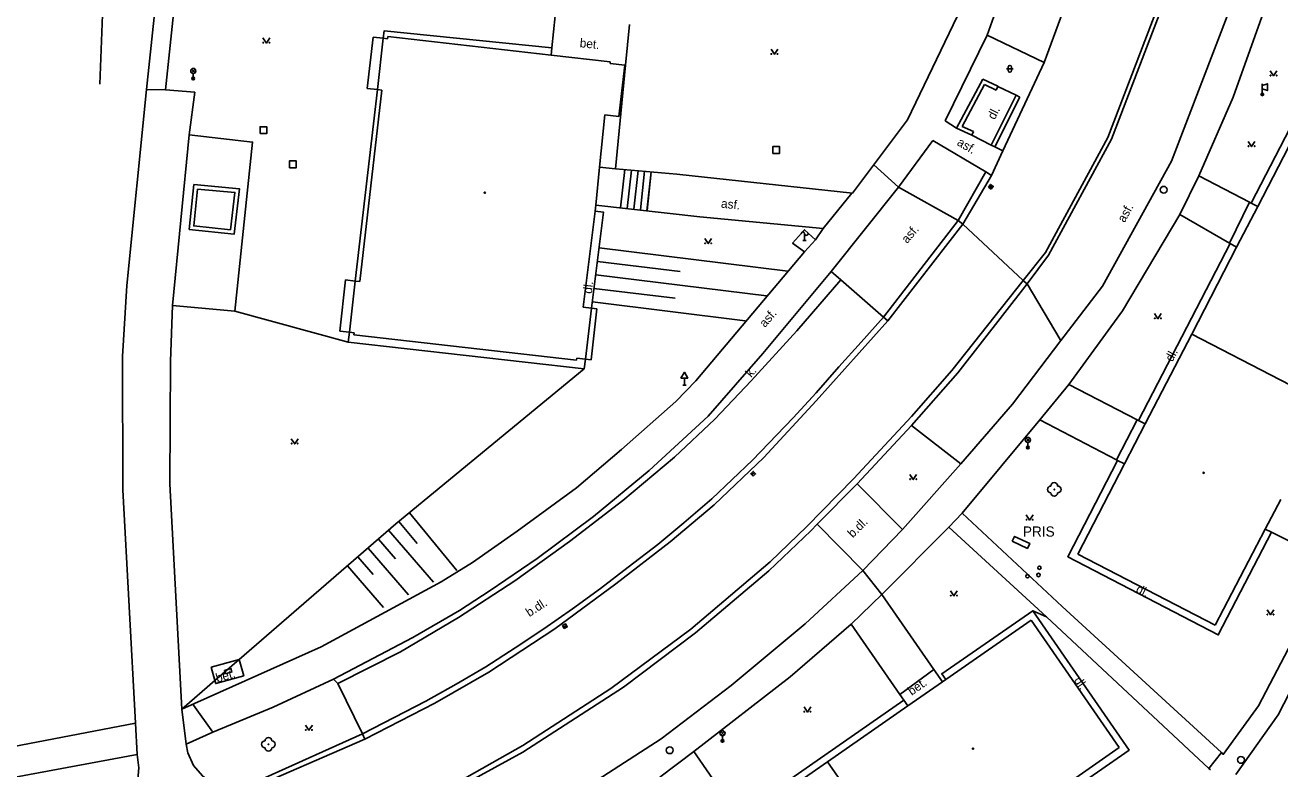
# Model space of a CAD drawing. Extents: x -602419 to -601554, y -1162937 to -1162362.
# Drawn here: x -601838.6 to -601746.3, y -1162548.7 to -1162494 of the extents above; entities that cross this region are included whole.
import ezdxf

# ---------------------------------------------------------------- set-up
doc = ezdxf.new("R2010")
doc.units = 0
doc.layers.add('Podklad', color=7, linetype='Continuous')

msp = doc.modelspace()

# ---------------------------------------------------------------- linework, layer by layer
at = {"layer": 'Podklad'}
for p, q in [((-601826.3725, -1162497.51), (-601826.1075, -1162497.245)), ((-601826.3725, -1162497.245), (-601826.1075, -1162497.51)), ((-601826.24, -1162497.565), (-601826.24, -1162497.94)), ((-601766.433, -1162497.228), (-601765.933, -1162497.228)), ((-601766.308, -1162497.103), (-601766.308, -1162497.353)), ((-601766.058, -1162497.103), (-601766.058, -1162497.353)), ((-601747.62, -1162499), (-601747.62, -1162498.325)), ((-601767.6543, -1162506.0005), (-601767.5057, -1162505.7995)), ((-601781.28, -1162509.85), (-601781.28, -1162509.35)), ((-601781.155, -1162509.85), (-601781.405, -1162509.85)), ((-601790.245, -1162520.48), (-601789.995, -1162520.48)), ((-601790.12, -1162519.971), (-601790.12, -1162520.48)), ((-601764.9925, -1162524.65), (-601764.7275, -1162524.385)), ((-601764.9925, -1162524.385), (-601764.7275, -1162524.65)), ((-601764.86, -1162524.705), (-601764.86, -1162525.08)), ((-601785.1504, -1162527.0964), (-601784.9696, -1162526.9236)), ((-601799.0184, -1162538.282), (-601798.8014, -1162538.1578)), ((-601787.4525, -1162546.22), (-601787.1875, -1162545.955)), ((-601787.4525, -1162545.955), (-601787.1875, -1162546.22)), ((-601787.32, -1162546.275), (-601787.32, -1162546.65))]:
    msp.add_line(p, q, dxfattribs=at)
for points in [[(-601718.62, -1162386.7199), (-601719.1599, -1162386.65), (-601718.15, -1162413.82), (-601705.36, -1162413.11), (-601705.25, -1162448.94), (-601717.05, -1162449.02), (-601716.04, -1162480.32), (-601716.4099, -1162484.2199), (-601717.94, -1162489.4099), (-601746.45, -1162544.74), (-601749.56, -1162549.13)], [(-601763.6599, -1162496.77), (-601760.48, -1162488.08), (-601756.88, -1162477.28)], [(-601848, -1162480.38), (-601847.54, -1162480.87), (-601842.9, -1162481.43), (-601833.56, -1162485.27), (-601831.9699, -1162485.6), (-601828.34, -1162485.99), (-601829.67, -1162498.74), (-601831.12, -1162513.1599), (-601831.45, -1162518.38), (-601831.42, -1162528.19), (-601830.48, -1162545.34)], [(-601833.1, -1162498.35), (-601832.63, -1162485.58), (-601829.24, -1162485.94)], [(-601828.28, -1162498.78), (-601826.96, -1162486.1599)], [(-601764.78, -1162486.14), (-601767.86, -1162494.76)], [(-601753.73, -1162488.54), (-601758.99, -1162502.27), (-601763.57, -1162510.73), (-601765.2151, -1162512.8049), (-601770.46, -1162519.42), (-601773.43, -1162522.8), (-601777.69, -1162527.38), (-601781.11, -1162530.89), (-601783.81, -1162533.48), (-601789.65, -1162538.44), (-601795.53, -1162542.8), (-601801.99, -1162546.98), (-601807.25, -1162549.95), (-601810.9, -1162551.81), (-601819.27, -1162555.34), (-601821.43, -1162556.31)], [(-601753.44, -1162488.63), (-601758.71, -1162502.4), (-601763.35, -1162510.94), (-601764.92, -1162513.03), (-601770.02, -1162519.59), (-601773.42, -1162523.45)], [(-601769.8, -1162526.28), (-601765.98, -1162521.88), (-601762.4303, -1162517.217), (-601759.38, -1162513.21), (-601754.29, -1162504.02), (-601748.9, -1162489.95)], [(-601746.9099, -1162491.32), (-601749.77, -1162499.32), (-601752.3, -1162505.09)], [(-601790.68, -1162504.9699), (-601777.76, -1162506.38), (-601773.7199, -1162500.98), (-601769.74, -1162492.7199)], [(-601799.87, -1162495.69), (-601799.63, -1162493.34)], [(-601794.16, -1162493.96), (-601794.45, -1162496.96), (-601795.18, -1162504.57)], [(-601813.44, -1162498.67), (-601813.01, -1162494.89)], [(-601813.01, -1162494.89), (-601812.27, -1162494.9699)], [(-601812.27, -1162494.9699), (-601812.21, -1162494.44), (-601799.87, -1162495.69)], [(-601811.95, -1162495.01), (-601811.93, -1162494.84)], [(-601811.93, -1162494.84), (-601799.92, -1162496.21)], [(-601767.86, -1162494.76), (-601770.95, -1162501.04)], [(-601763.6599, -1162496.77), (-601767.86, -1162494.76)], [(-601748.44, -1162507.1), (-601741.68, -1162494.03)], [(-601821.11, -1162494.955), (-601820.86, -1162495.33), (-601820.61, -1162494.955)], [(-601812.7, -1162498.75), (-601812.27, -1162494.9699)], [(-601811.95, -1162495.01), (-601812.27, -1162494.9699)], [(-601799.92, -1162496.21), (-601799.87, -1162495.69)], [(-601783.75, -1162495.7849), (-601783.5, -1162496.1599), (-601783.25, -1162495.7849)], [(-601799.92, -1162496.21), (-601795.57, -1162496.7)], [(-601795.57, -1162496.7), (-601795.58, -1162496.84)], [(-601766.69, -1162503.25), (-601763.6599, -1162496.77)], [(-601795.58, -1162496.84), (-601794.51, -1162496.96)], [(-601794.51, -1162496.96), (-601794.94, -1162500.73)], [(-601794.51, -1162496.96), (-601794.45, -1162496.96)], [(-601747.04, -1162497.365), (-601746.79, -1162497.74), (-601746.54, -1162497.365)], [(-601770.11, -1162501.6), (-601768.18, -1162497.98)], [(-601769.7, -1162501.46), (-601768.05, -1162498.38)], [(-601768.18, -1162497.98), (-601767.08, -1162498.51)], [(-601768.05, -1162498.38), (-601767.2, -1162498.79)], [(-601767.2, -1162498.79), (-601767.07, -1162498.52)], [(-601767.08, -1162498.51), (-601767.07, -1162498.52)], [(-601767.07, -1162498.52), (-601765.71, -1162499.17)], [(-601747.62, -1162498.45), (-601747.245, -1162498.325), (-601747.245, -1162498.825), (-601747.62, -1162498.7)], [(-601828.28, -1162498.78), (-601829.67, -1162498.74)], [(-601826.12, -1162498.94), (-601828.28, -1162498.78)], [(-601826.53, -1162502.08), (-601826.12, -1162498.94)], [(-601814.32, -1162512.83), (-601812.7, -1162498.75)], [(-601813.98, -1162512.87), (-601812.38, -1162498.79)], [(-601812.7, -1162498.75), (-601813.44, -1162498.67)], [(-601812.38, -1162498.79), (-601812.7, -1162498.75)], [(-601765.71, -1162499.17), (-601767.56, -1162502.83)], [(-601765.44, -1162499.3), (-601767.3, -1162502.96)], [(-601765.71, -1162499.17), (-601765.44, -1162499.3)], [(-601795.9699, -1162500.61), (-601796.36, -1162504.46)], [(-601794.94, -1162500.73), (-601795.9699, -1162500.61)], [(-601770.95, -1162501.04), (-601770.11, -1162501.6)], [(-601747.95, -1162507.35), (-601744.53, -1162500.75)], [(-601826.53, -1162502.08), (-601821.88, -1162502.61), (-601823.17, -1162515.06), (-601827.76, -1162514.62)], [(-601827.76, -1162514.62), (-601826.53, -1162502.08)], [(-601768.99, -1162502.11), (-601770.11, -1162501.6)], [(-601768.87, -1162501.84), (-601769.7, -1162501.46)], [(-601768.99, -1162502.11), (-601768.87, -1162501.84)], [(-601767.56, -1162502.83), (-601768.99, -1162502.11)], [(-601771.85, -1162502.5), (-601774.38, -1162505.92), (-601779.32, -1162512.13)], [(-601771.85, -1162502.5), (-601767.95, -1162504.81)], [(-601767.3, -1162502.96), (-601767.56, -1162502.83)], [(-601767.3, -1162502.96), (-601766.69, -1162503.25)], [(-601748.6599, -1162502.565), (-601748.4099, -1162502.94), (-601748.1599, -1162502.565)], [(-601767.54, -1162505.06), (-601766.69, -1162503.25)], [(-601796.36, -1162504.46), (-601796.63, -1162507.25)], [(-601796.36, -1162504.46), (-601795.18, -1162504.57)], [(-601795.18, -1162504.57), (-601790.68, -1162504.9699)], [(-601794.49, -1162504.63), (-601794.83, -1162507.44)], [(-601794.34, -1162507.49), (-601794.01, -1162504.67)], [(-601793.53, -1162504.71), (-601793.85, -1162507.54)], [(-601793.36, -1162507.59), (-601793.05, -1162504.76)], [(-601792.8731, -1162507.6674), (-601792.5702, -1162504.8019)], [(-601792.57, -1162504.8), (-601792.87, -1162507.64)], [(-601774.38, -1162505.92), (-601776.1964, -1162504.2901)], [(-601767.95, -1162504.81), (-601769.98, -1162508.37), (-601775.48, -1162515.48)], [(-601775.17, -1162515.77), (-601769.64, -1162508.64), (-601767.54, -1162505.06)], [(-601767.95, -1162504.81), (-601767.54, -1162505.06)], [(-601752.3, -1162505.09), (-601753.69, -1162507.95)], [(-601752.3, -1162505.09), (-601748.55, -1162507.04)], [(-601826.19, -1162505.74), (-601822.84, -1162506.04), (-601823.24, -1162509.39), (-601826.53, -1162509.04), (-601826.19, -1162505.74)], [(-601769.98, -1162508.37), (-601774.38, -1162505.92)], [(-601825.93, -1162506.07), (-601823.17, -1162506.31), (-601823.5, -1162509.06), (-601826.2, -1162508.78), (-601825.93, -1162506.07)], [(-601779.92, -1162508.96), (-601777.8116, -1162506.3744)], [(-601796.68, -1162507.69), (-601797.57, -1162514.76)], [(-601796.68, -1162507.69), (-601796.08, -1162507.76), (-601796.94, -1162514.83)], [(-601796.63, -1162507.25), (-601796.68, -1162507.69)], [(-601779.92, -1162508.96), (-601788.98, -1162508.1), (-601796.63, -1162507.25)], [(-601750.04, -1162510.04), (-601748.55, -1162507.04)], [(-601749.51, -1162510.35), (-601747.95, -1162507.35)], [(-601748.55, -1162507.04), (-601748.44, -1162507.1)], [(-601748.44, -1162507.1), (-601747.95, -1162507.35)], [(-601769.98, -1162508.37), (-601769.64, -1162508.6399), (-601765.2151, -1162512.8049)], [(-601753.69, -1162507.95), (-601757.9099, -1162515.03), (-601761.85, -1162520.43)], [(-601750.04, -1162510.04), (-601753.69, -1162507.95)], [(-601788.62, -1162509.705), (-601788.37, -1162510.08), (-601788.12, -1162509.705)], [(-601781.29, -1162510.68), (-601782.17, -1162510.04), (-601781.28, -1162509.06), (-601780.48, -1162509.79)], [(-601780.48, -1162509.79), (-601779.92, -1162508.96)], [(-601796.4, -1162510.39), (-601782.51, -1162512.1)], [(-601781.29, -1162510.68), (-601780.48, -1162509.79)], [(-601756.73, -1162523.08), (-601749.99, -1162510.08)], [(-601752.81, -1162516.73), (-601749.51, -1162510.35)], [(-601749.99, -1162510.08), (-601750.04, -1162510.04)], [(-601749.51, -1162510.35), (-601749.99, -1162510.08)], [(-601796.52, -1162511.39), (-601790.42, -1162512.13)], [(-601790.74, -1162521.68), (-601789.29, -1162520.1599), (-601781.29, -1162510.68)], [(-601796.64, -1162512.38), (-601784.07, -1162513.92)], [(-601779.32, -1162512.13), (-601784.35, -1162518.1599), (-601788.37, -1162522.76)], [(-601778.62, -1162512.75), (-601779.32, -1162512.13)], [(-601778.62, -1162512.75), (-601781.86, -1162516.49), (-601785.2199, -1162520.17), (-601787.88, -1162523), (-601790.84, -1162525.78), (-601794.64, -1162528.96), (-601798.58, -1162531.99), (-601802.59, -1162534.88), (-601806.73, -1162537.57), (-601811.01, -1162540.09), (-601815.6, -1162542.42)], [(-601815.4699, -1162516.51), (-601815.04, -1162512.74)], [(-601815.04, -1162512.74), (-601814.32, -1162512.83)], [(-601814.76, -1162516.59), (-601814.32, -1162512.83)], [(-601814.32, -1162512.83), (-601813.98, -1162512.87)], [(-601796.77, -1162513.37), (-601790.8, -1162514.1)], [(-601775.48, -1162515.48), (-601778.62, -1162512.75)], [(-601762.4303, -1162517.217), (-601762.476, -1162517.1401), (-601764.92, -1162513.03), (-601765.1241, -1162512.8741), (-601765.2151, -1162512.8049)], [(-601827.09, -1162544.31), (-601827.95, -1162527.74), (-601827.9, -1162518.73), (-601827.76, -1162514.62)], [(-601823.17, -1162515.06), (-601814.84, -1162517.32)], [(-601797.57, -1162514.76), (-601796.94, -1162514.83)], [(-601796.94, -1162514.83), (-601797.4, -1162518.57)], [(-601796.55, -1162514.88), (-601796.9699, -1162518.62)], [(-601796.94, -1162514.83), (-601796.55, -1162514.88)], [(-601796.89, -1162514.37), (-601785.64, -1162515.75)], [(-601755.55, -1162515.225), (-601755.3, -1162515.6), (-601755.05, -1162515.225)], [(-601775.17, -1162515.77), (-601780.43, -1162521.65), (-601784.27, -1162525.82), (-601787.93, -1162529.28), (-601791.1599, -1162532)], [(-601785.11, -1162526), (-601782.11, -1162522.89), (-601780.43, -1162521.05), (-601778.77, -1162519.14), (-601777.13, -1162517.33), (-601775.48, -1162515.48)], [(-601775.17, -1162515.77), (-601775.48, -1162515.48)], [(-601814.76, -1162516.59), (-601815.4699, -1162516.51)], [(-601797.49, -1162519.3), (-601814.84, -1162517.32), (-601814.76, -1162516.59)], [(-601814.4, -1162516.63), (-601814.76, -1162516.59)], [(-601814.42, -1162516.78), (-601814.4, -1162516.63)], [(-601798.06, -1162518.64), (-601814.42, -1162516.78)], [(-601756.24, -1162523.34), (-601752.81, -1162516.73)], [(-601742.6599, -1162521.99), (-601752.81, -1162516.73)], [(-601798.04, -1162518.5), (-601798.06, -1162518.64)], [(-601797.4, -1162518.57), (-601798.04, -1162518.5)], [(-601797.4, -1162518.57), (-601797.49, -1162519.3)], [(-601796.9699, -1162518.62), (-601797.4, -1162518.57)], [(-601797.49, -1162519.3), (-601811.33, -1162530.7), (-601822.85, -1162540.6599)], [(-601761.85, -1162520.43), (-601763.99, -1162523.05)], [(-601756.82, -1162523.04), (-601761.85, -1162520.43)], [(-601802.4099, -1162531.2199), (-601798.05, -1162528.03), (-601794.74, -1162525.2199), (-601790.74, -1162521.68)], [(-601788.37, -1162522.76), (-601792.7, -1162526.76), (-601796.81, -1162530.14)], [(-601773.42, -1162523.45), (-601777.4099, -1162527.74)], [(-601773.42, -1162523.45), (-601769.8, -1162526.28)], [(-601746.94, -1162531.3), (-601742.42, -1162533.57), (-601747.9, -1162544.08), (-601750.49, -1162547.64), (-601750.6322, -1162547.5095), (-601762.35, -1162536.76), (-601769.69, -1162529.9), (-601763.99, -1162523.05)], [(-601758.34, -1162525.98), (-601763.99, -1162523.05)], [(-601756.82, -1162523.04), (-601758.34, -1162525.98)], [(-601757.76, -1162526.28), (-601756.24, -1162523.34)], [(-601756.73, -1162523.08), (-601756.82, -1162523.04)], [(-601756.24, -1162523.34), (-601756.73, -1162523.08)], [(-601819.03, -1162524.435), (-601818.78, -1162524.81), (-601818.53, -1162524.435)], [(-601785.11, -1162526), (-601788.11, -1162528.84), (-601790.15, -1162530.61), (-601792.07, -1162532.21), (-601794.25, -1162533.87), (-601796.3, -1162535.44), (-601798.35, -1162536.94)], [(-601774.07, -1162531.1), (-601769.8, -1162526.28)], [(-601746.94, -1162531.3), (-601750.86, -1162538.86), (-601761.93, -1162533.11), (-601758.26, -1162526.02)], [(-601761.19, -1162532.9099), (-601757.76, -1162526.28)], [(-601758.26, -1162526.02), (-601758.34, -1162525.98)], [(-601757.76, -1162526.28), (-601758.26, -1162526.02)], [(-601773.54, -1162527.055), (-601773.29, -1162527.43), (-601773.04, -1162527.055)], [(-601780.35, -1162530.7199), (-601777.4099, -1162527.74)], [(-601777.4099, -1162527.74), (-601774.07, -1162531.1)], [(-601746.26, -1162528.9), (-601747.4, -1162531.07)], [(-601810.33, -1162529.88), (-601806.85, -1162534.11)], [(-601769.69, -1162529.9), (-601770.67, -1162530.94)], [(-601821.33, -1162556.6), (-601814.18, -1162553.71), (-601808.95, -1162551.28), (-601801.99, -1162547.4699), (-601794.61, -1162542.7), (-601789.3, -1162538.71), (-601783.92, -1162534.14), (-601780.82, -1162531.21), (-601780.35, -1162530.7199)], [(-601811.11, -1162530.52), (-601809.77, -1162532.14)], [(-601796.81, -1162530.14), (-601800.95, -1162533.24), (-601804.4099, -1162535.59)], [(-601780.35, -1162530.7199), (-601777, -1162534.12)], [(-601764.98, -1162530.0349), (-601764.73, -1162530.4099), (-601764.48, -1162530.0349)], [(-601812.62, -1162531.82), (-601811.37, -1162533.27)], [(-601811.87, -1162531.1599), (-601808.57, -1162534.98)], [(-601805.7, -1162533.53), (-601802.4099, -1162531.2199)], [(-601777, -1162534.12), (-601774.07, -1162531.1)], [(-601775.6, -1162535.89), (-601770.67, -1162530.94)], [(-601770.67, -1162530.94), (-601763.49, -1162537.53)], [(-601766.01, -1162531.9699), (-601765.84, -1162531.61), (-601764.7199, -1162532.13), (-601764.89, -1162532.49), (-601766.01, -1162531.9699)], [(-601747.4, -1162531.07), (-601751.09, -1162538.13)], [(-601747.4, -1162531.07), (-601746.94, -1162531.3)], [(-601813.61, -1162546.52), (-601808.4699, -1162543.87), (-601804.5, -1162541.59), (-601799.64, -1162538.4), (-601795.15, -1162535.1), (-601791.1599, -1162532)], [(-601813.38, -1162532.4699), (-601810.4099, -1162535.9099)], [(-601827.09, -1162544.31), (-601816.84, -1162539.73), (-601808, -1162534.95), (-601805.7, -1162533.53)], [(-601814.14, -1162533.12), (-601813.02, -1162534.42)], [(-601751.09, -1162538.13), (-601761.19, -1162532.9099)], [(-601777, -1162534.12), (-601781.25, -1162538.05), (-601786.67, -1162542.57), (-601791.84, -1162546.51), (-601798.82, -1162551), (-601806.92, -1162555.44), (-601811.79, -1162557.77), (-601819.34, -1162560.84)], [(-601814.89, -1162533.78), (-601812.26, -1162536.83)], [(-601777.86, -1162538.07), (-601775.6, -1162535.89), (-601777, -1162534.12)], [(-601804.4099, -1162535.59), (-601806.6599, -1162537.05), (-601810.08, -1162539.04), (-601815.92, -1162542.1)], [(-601775.6, -1162535.89), (-601771.77, -1162541.4099)], [(-601770.55, -1162535.615), (-601770.3, -1162535.99), (-601770.05, -1162535.615)], [(-601798.35, -1162536.94), (-601800.46, -1162538.42), (-601802.56, -1162539.8), (-601804.73, -1162541.21), (-601806.9099, -1162542.49), (-601809.14, -1162543.7199), (-601813.79, -1162546.13)], [(-601770.89, -1162542.14), (-601771.19, -1162541.71), (-601764.49, -1162537.08), (-601757.42, -1162547.33), (-601764.39, -1162552.18)], [(-601764.49, -1162537.08), (-601763.49, -1162537.53)], [(-601747.27, -1162537.005), (-601747.02, -1162537.38), (-601746.77, -1162537.005)], [(-601777.86, -1162538.07), (-601782.33, -1162541.93), (-601789.43, -1162547.44)], [(-601777.86, -1162538.07), (-601774.28, -1162543.23)], [(-601770.89, -1162542.14), (-601764.62, -1162537.78)], [(-601764.62, -1162537.78), (-601758.14, -1162547.13)], [(-601763.49, -1162537.53), (-601751.5572, -1162548.6712), (-601751.43, -1162548.79)], [(-601824.92, -1162541.23), (-601822.85, -1162540.6599)], [(-601822.85, -1162540.6599), (-601824.65, -1162542.2)], [(-601822.85, -1162540.6599), (-601822.52, -1162541.86), (-601824.58, -1162542.44), (-601824.65, -1162542.2)], [(-601824.65, -1162542.2), (-601824.92, -1162541.23)], [(-601774.28, -1162543.23), (-601771.77, -1162541.4099)], [(-601771.77, -1162541.4099), (-601771.14, -1162542.31)], [(-601824.65, -1162542.2), (-601827.09, -1162544.31)], [(-601815.92, -1162542.1), (-601820.36, -1162544.1599), (-601824.81, -1162546), (-601826.77, -1162546.89)], [(-601815.92, -1162542.1), (-601815.6, -1162542.42)], [(-601815.6, -1162542.42), (-601813.79, -1162546.13)], [(-601773.69, -1162544.08), (-601771.14, -1162542.31)], [(-601771.14, -1162542.31), (-601770.89, -1162542.14)], [(-601785.63, -1162552.38), (-601785.93, -1162551.96), (-601773.98, -1162543.6599)], [(-601774.28, -1162543.23), (-601773.98, -1162543.6599)], [(-601773.98, -1162543.6599), (-601773.69, -1162544.08)], [(-601826.77, -1162546.89), (-601827.09, -1162544.31)], [(-601824.81, -1162546), (-601826.22, -1162544.0299), (-601826.2789, -1162543.9476)], [(-601781.32, -1162544.155), (-601781.07, -1162544.53), (-601780.82, -1162544.155)], [(-601779.59, -1162548.18), (-601773.69, -1162544.08)], [(-601830.48, -1162545.34), (-601842.52, -1162547.6599)], [(-601830.48, -1162545.34), (-601830.36, -1162547.65)], [(-601817.98, -1162545.495), (-601817.73, -1162545.87), (-601817.48, -1162545.495)], [(-601822.88, -1162550.2199), (-601813.79, -1162546.13)], [(-601813.61, -1162546.52), (-601822.76, -1162550.5)], [(-601813.79, -1162546.13), (-601813.61, -1162546.52)], [(-601826.77, -1162546.89), (-601826.63, -1162547.54), (-601826.2199, -1162548.46), (-601825.57, -1162549.23), (-601825.19, -1162549.51), (-601824.65, -1162549.84), (-601824.06, -1162550.06), (-601823.45, -1162550.2199), (-601822.88, -1162550.2199)], [(-601789.43, -1162547.44), (-601791.93, -1162549.31)], [(-601786.46, -1162551.7199), (-601789.43, -1162547.44)], [(-601758.14, -1162547.13), (-601764.7, -1162551.73)], [(-601751.5572, -1162548.6712), (-601750.6322, -1162547.5095)], [(-601842.12, -1162549.83), (-601830.36, -1162547.65)], [(-601834.37, -1162553.56), (-601833.44, -1162553.31), (-601832.59, -1162552.88), (-601831.83, -1162552.29), (-601831.19, -1162551.58), (-601830.8, -1162550.93), (-601830.55, -1162550.35), (-601830.32, -1162549.5), (-601830.25, -1162548.63), (-601830.36, -1162547.65)], [(-601785.63, -1162552.38), (-601779.59, -1162548.18)], [(-601773.05, -1162557.59), (-601779.59, -1162548.18)]]:
    msp.add_lwpolyline(points, dxfattribs=at)
for points in [[(-601821.33, -1162501.99), (-601820.83, -1162501.99), (-601820.83, -1162501.49), (-601821.33, -1162501.49)], [(-601783.62, -1162503.45), (-601783.12, -1162503.45), (-601783.12, -1162502.95), (-601783.62, -1162502.95)], [(-601819.17, -1162504.5), (-601818.67, -1162504.5), (-601818.67, -1162504), (-601819.17, -1162504)], [(-601767.5538, -1162506.0748), (-601767.4052, -1162505.8738), (-601767.6062, -1162505.7252), (-601767.7548, -1162505.9262)], [(-601790.37, -1162519.971), (-601789.87, -1162519.971), (-601790.12, -1162519.538)], [(-601785.064, -1162527.1867), (-601784.8833, -1162527.014), (-601785.056, -1162526.8333), (-601785.2367, -1162527.006)], [(-601798.9563, -1162538.3905), (-601798.7393, -1162538.2663), (-601798.8635, -1162538.0493), (-601799.0805, -1162538.1735)], [(-601823.8768, -1162541.7081), (-601823.3955, -1162541.5726), (-601823.4632, -1162541.3319), (-601823.9445, -1162541.4674)]]:
    msp.add_lwpolyline(points, close=True, dxfattribs=at)
for centre, radius in [((-601821.0851, -1162495.3049), 0.025), ((-601820.6354, -1162495.3049), 0.025), ((-601783.7251, -1162496.1348), 0.025), ((-601783.2754, -1162496.1348), 0.025), ((-601826.24, -1162497.3775), 0.1875), ((-601747.0151, -1162497.7149), 0.025), ((-601746.5654, -1162497.7149), 0.025), ((-601826.24, -1162497.94), 0.1), ((-601826.24, -1162497.94), 0.0723), ((-601826.24, -1162497.94), 0.0438), ((-601747.62, -1162499.1), 0.1), ((-601747.62, -1162499.1), 0.0723), ((-601747.62, -1162499.1), 0.0438), ((-601748.635, -1162502.9149), 0.025), ((-601748.1853, -1162502.9149), 0.025), ((-601754.87, -1162506.12), 0.25), ((-601804.8, -1162506.33), 0.045), ((-601804.8, -1162506.33), 0.0199), ((-601788.5951, -1162510.0549), 0.025), ((-601788.1454, -1162510.0549), 0.025), ((-601755.5251, -1162515.5749), 0.025), ((-601755.0754, -1162515.5749), 0.025), ((-601764.86, -1162524.5175), 0.1875), ((-601819.0051, -1162524.7849), 0.025), ((-601818.5554, -1162524.7849), 0.025), ((-601764.86, -1162525.08), 0.1), ((-601764.86, -1162525.08), 0.0723), ((-601764.86, -1162525.08), 0.0438), ((-601751.93, -1162526.94), 0.045), ((-601751.93, -1162526.94), 0.0199), ((-601773.5151, -1162527.4049), 0.025), ((-601773.0654, -1162527.4049), 0.025), ((-601762.92, -1162528.1599), 0.025), ((-601764.9551, -1162530.3848), 0.025), ((-601764.5054, -1162530.3848), 0.025), ((-601764.89, -1162534.54), 0.125), ((-601764.08, -1162534.45), 0.125), ((-601764.01, -1162533.92), 0.125), ((-601770.5251, -1162535.9649), 0.025), ((-601770.0754, -1162535.9649), 0.025), ((-601747.2451, -1162537.3549), 0.025), ((-601746.7954, -1162537.3549), 0.025), ((-601781.2951, -1162544.5049), 0.025), ((-601780.8454, -1162544.5049), 0.025), ((-601817.9551, -1162545.8449), 0.025), ((-601817.5054, -1162545.8449), 0.025), ((-601787.32, -1162546.0875), 0.1875), ((-601787.32, -1162546.65), 0.1), ((-601787.32, -1162546.65), 0.0723), ((-601787.32, -1162546.65), 0.0438), ((-601820.71, -1162546.9), 0.025), ((-601791.2, -1162547.34), 0.25), ((-601768.9, -1162547.2199), 0.045), ((-601768.9, -1162547.2199), 0.0199), ((-601749.19, -1162548.05), 0.25)]:
    msp.add_circle(centre, radius, dxfattribs=at)
for centre, radius, start, end in [((-601766.1828, -1162497.1032), 0.125, 0, 180), ((-601766.1828, -1162497.3532), 0.125, 180, 0), ((-601781.405, -1162509.35), 0.125, 0, 180), ((-601781.155, -1162509.35), 0.125, 180, 0), ((-601763.17, -1162528.1599), 0.25, 90, 270), ((-601762.92, -1162527.9099), 0.25, 0, 180), ((-601762.67, -1162528.1599), 0.25, 270, 90), ((-601762.92, -1162528.4099), 0.25, 180, 0), ((-601820.71, -1162546.65), 0.25, 0, 180), ((-601820.96, -1162546.9), 0.25, 90, 270), ((-601820.71, -1162547.15), 0.25, 180, 0), ((-601820.46, -1162546.9), 0.25, 270, 90)]:
    msp.add_arc(centre, radius, start, end, dxfattribs=at)

# ---------------------------------------------------------------- texts
for s, rotation, p in [('bet.', 354.24, (-601797.84, -1162495.63)), ('dl.', 63.06, (-601767.3, -1162501.01)), ('asf.', 329.29, (-601770.13, -1162502.8)), ('asf.', 353.94, (-601787.45, -1162507.43)), ('asf.', 61.02, (-601757.75, -1162508.58)), ('asf.', 49.34, (-601773.74, -1162510.11)), ('dl.', 83.61, (-601796.93, -1162513.79)), ('asf.', 49.34, (-601784.19, -1162516.29)), ('dl.', 62.59, (-601754.23, -1162518.82)), ('k. ', 48.68, (-601785.21, -1162519.96)), ('b.dl.', 44.62, (-601777.74, -1162531.75)), ('dl.', 332.67, (-601756.9699, -1162535.68)), ('b.dl.', 32.98, (-601801.52, -1162537.55)), ('bet.', 15.72, (-601824.48, -1162542.36)), ('dl.', 304.72, (-601761.5, -1162542.2)), ('bet.', 34.92, (-601773.4099, -1162543.34))]:
    msp.add_text(s, height=0.65, rotation=rotation, dxfattribs=at).set_placement(p)
msp.add_text('PRIS', height=0.75, dxfattribs=at).set_placement((-601765.23, -1162531.63))

doc.saveas('drawing.dxf')
